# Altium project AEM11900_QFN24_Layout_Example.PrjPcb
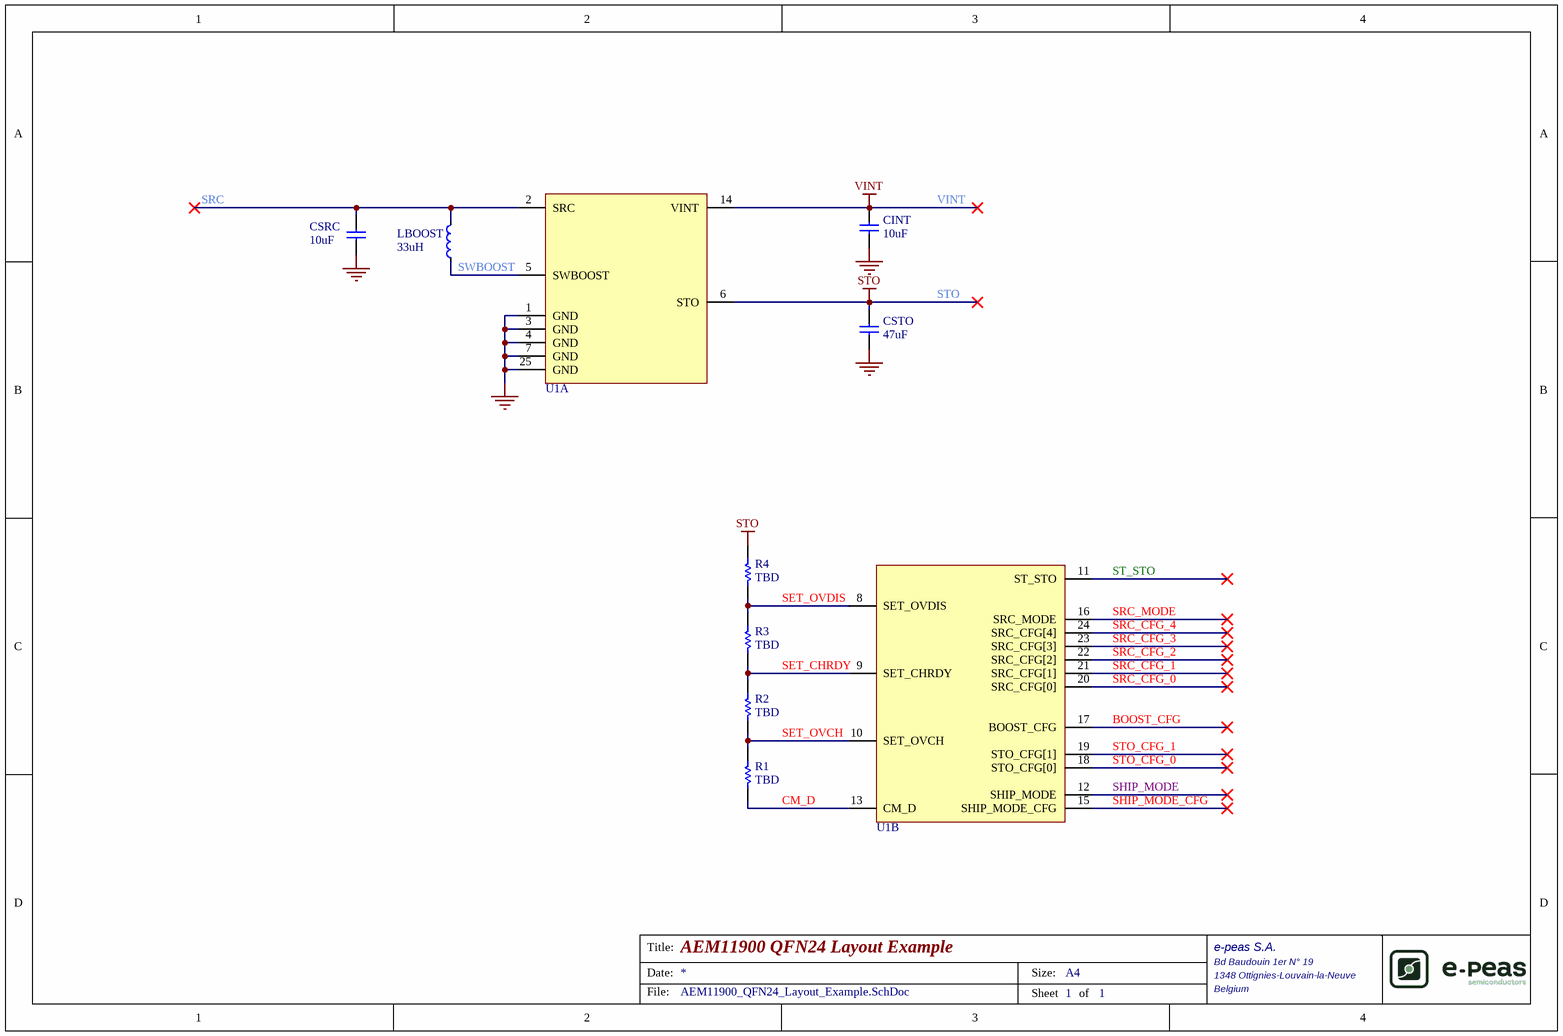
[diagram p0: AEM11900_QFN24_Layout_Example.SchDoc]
Address1_Global: Bd Baudouin 1er N° 19; Address2_Global: 1348 Ottignies-Louvain-la-Neuve; Address3_Global: Belgium; Name: AEM11900 QFN24 Layout Example; Organization_Global: e-peas S.A.; Website_Global: https://e-peas.com
1 sheet, 9 parts. Net scope: global (net labels, ports and power ports of the same name join across sheets).
Board file: AEM11900_QFN24_Layout_Example.PcbDoc

## Sheet AEM11900_QFN24_Layout_Example.SchDoc
size A4; DocumentNumber: 1; SheetNumber: 1; SheetTotal: 1; Organization: e-peas S.A.; Address1: The Gate Business Center; Address2: rue Cattelain 1 b4,; Address3: 1435 Mont-St-Guibert; Address4: Belgium

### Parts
CINT  10uF  [C0402_[1005]]
CSRC  10uF  [C0603_[1608]]
CSTO  47uF  [C0603_[1608]]
LBOOST  33uH  [Coilcraft-LPS4018]
R1  TBD  [Resistor_0603_[1608]]
R2  TBD  [Resistor_0603_[1608]]
R3  TBD  [Resistor_0603_[1608]]
R4  TBD  [Resistor_0603_[1608]]
U1  AEM11900_QFN24  [QFN24_4x4mm_PITCH_0.5mm_PAD_2.45mm]  (value not drawn)  (parts A,B of 2)

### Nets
GND: CINT.1 CSRC.1 CSTO.1 U1.1(GND) U1.3(GND) U1.4(GND) U1.7(GND) U1.25(GND)
STO: CSTO.2 R4.2 U1.6(STO)
VINT: CINT.2 U1.14(VINT)
BOOST_CFG: U1.17(BOOST_CFG)
CM_D: R1.1 U1.13(CM_D)
SET_CHRDY: R2.2 R3.1 U1.9(SET_CHRDY)
SET_OVCH: R1.2 R2.1 U1.10(SET_OVCH)
SET_OVDIS: R3.2 R4.1 U1.8(SET_OVDIS)
SHIP_MODE: U1.12(SHIP_MODE)
SHIP_MODE_CFG: U1.15(SHIP_MODE_CFG)
SRC: CSRC.2 LBOOST.2 U1.2(SRC)
SRC_CFG_0: U1.20(SRC_CFG[0])
SRC_CFG_1: U1.21(SRC_CFG[1])
SRC_CFG_2: U1.22(SRC_CFG[2])
SRC_CFG_3: U1.23(SRC_CFG[3])
SRC_CFG_4: U1.24(SRC_CFG[4])
SRC_MODE: U1.16(SRC_MODE)
ST_STO: U1.11(ST_STO)
STO_CFG_0: U1.18(STO_CFG[0])
STO_CFG_1: U1.19(STO_CFG[1])
SWBOOST: LBOOST.1 U1.5(SWBOOST)

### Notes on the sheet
- Title:
- Date:
- Size:
- A4
- File:
- Sheet
- of

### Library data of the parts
CINT = Cap Ceramic 10uF, 6.3V, 20%, X5R, 0402: Manuf: MURATA; Manuf PN: GRM155R60J106ME05D; Package Metric: 1005
CSRC = Cap Ceramic 10uF, 10V, 20%, X5R 0603: Manuf: MURATA; Manuf PN: GRM188R61A106ME69D; Package Metric: 1608
CSTO = Cap Ceramic 47uF 6.3V +/-20% X5R 0603: Manuf: Murata; Manuf PN: GRM188R60J476ME15D; Package Metric: 1608
LBOOST = Power Inductor 33uH - 0.68A - LPS4018 - Small Symbol: Power Inductor 33uH - 0,68A - LPS4018; Manuf: Coilcraft; Manuf PN: LPS4018-333MRB; Tol: 20%; Rdc: 420mOhms; Self Resonant Frequency: 20MHz; Max DC Current: 800mA
R1-R4 = Resistor TBD - 0603: Mnt: SMD
U1 = AEM11900_QFN24: Manuf: e-peas; Manuf PN: 10AEM11900A0001; Mnt: SMD; Pitch: 0.5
